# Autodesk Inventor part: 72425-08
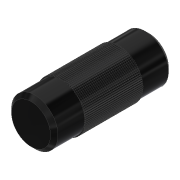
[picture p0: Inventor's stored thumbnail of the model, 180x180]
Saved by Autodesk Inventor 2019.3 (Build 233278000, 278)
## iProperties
Created: 2013-06
Part Number: 72425-08
Material: Ogólny
Document SubType Name: Modeling
Designer: CADENGINEERING4
Density: 1 g/cm^3
Appearance: Gładki — czarny
Author: CADENGINEERING4
Revision Number: ÈÎºÎ
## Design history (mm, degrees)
feature "ÊäÈë1"
node "Bryła1"
